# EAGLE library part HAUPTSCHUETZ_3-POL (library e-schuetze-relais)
Hauptschütz mit 3 Schließern
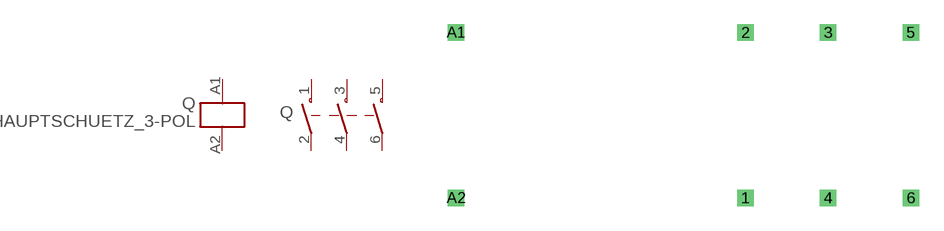
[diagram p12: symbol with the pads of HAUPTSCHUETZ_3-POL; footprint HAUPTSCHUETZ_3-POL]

Designator prefix Q; gates G$1=SPULE G$2=SCHLIESSER_HAUPTSCHUETZ_3-POL

## HAUPTSCHUETZ_3-POL  [HAUPTSCHUETZ_3-POL]
1  G$2:1  pas
2  G$2:2  pas
3  G$2:3  pas
4  G$2:4  pas
5  G$2:5  pas
6  G$2:6  pas
A1  G$1:A1  in
A2  G$1:A2  in

## Footprint HAUPTSCHUETZ_3-POL (pad centres in mm)
Dummy
drill 0.5 pad 1 square: 1 7.62,-7.62; 2 7.62,2.54; 3 12.7,2.54; 4 12.7,-7.62; 5 17.78,2.54; 6 17.78,-7.62; A1 -10.16,2.54; A2 -10.16,-7.62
